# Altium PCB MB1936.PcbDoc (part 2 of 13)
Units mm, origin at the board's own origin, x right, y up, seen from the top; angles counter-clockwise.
Board outline 172 x 137 mm, 6 copper layers (Top Layer, Signal Layer 1, Signal Layer 2, Signal Layer 3, Signal Layer 4, Bottom Layer), stack 1.549 mm thick; 859 components, 672 nets, 3477 pads, 2222 vias.
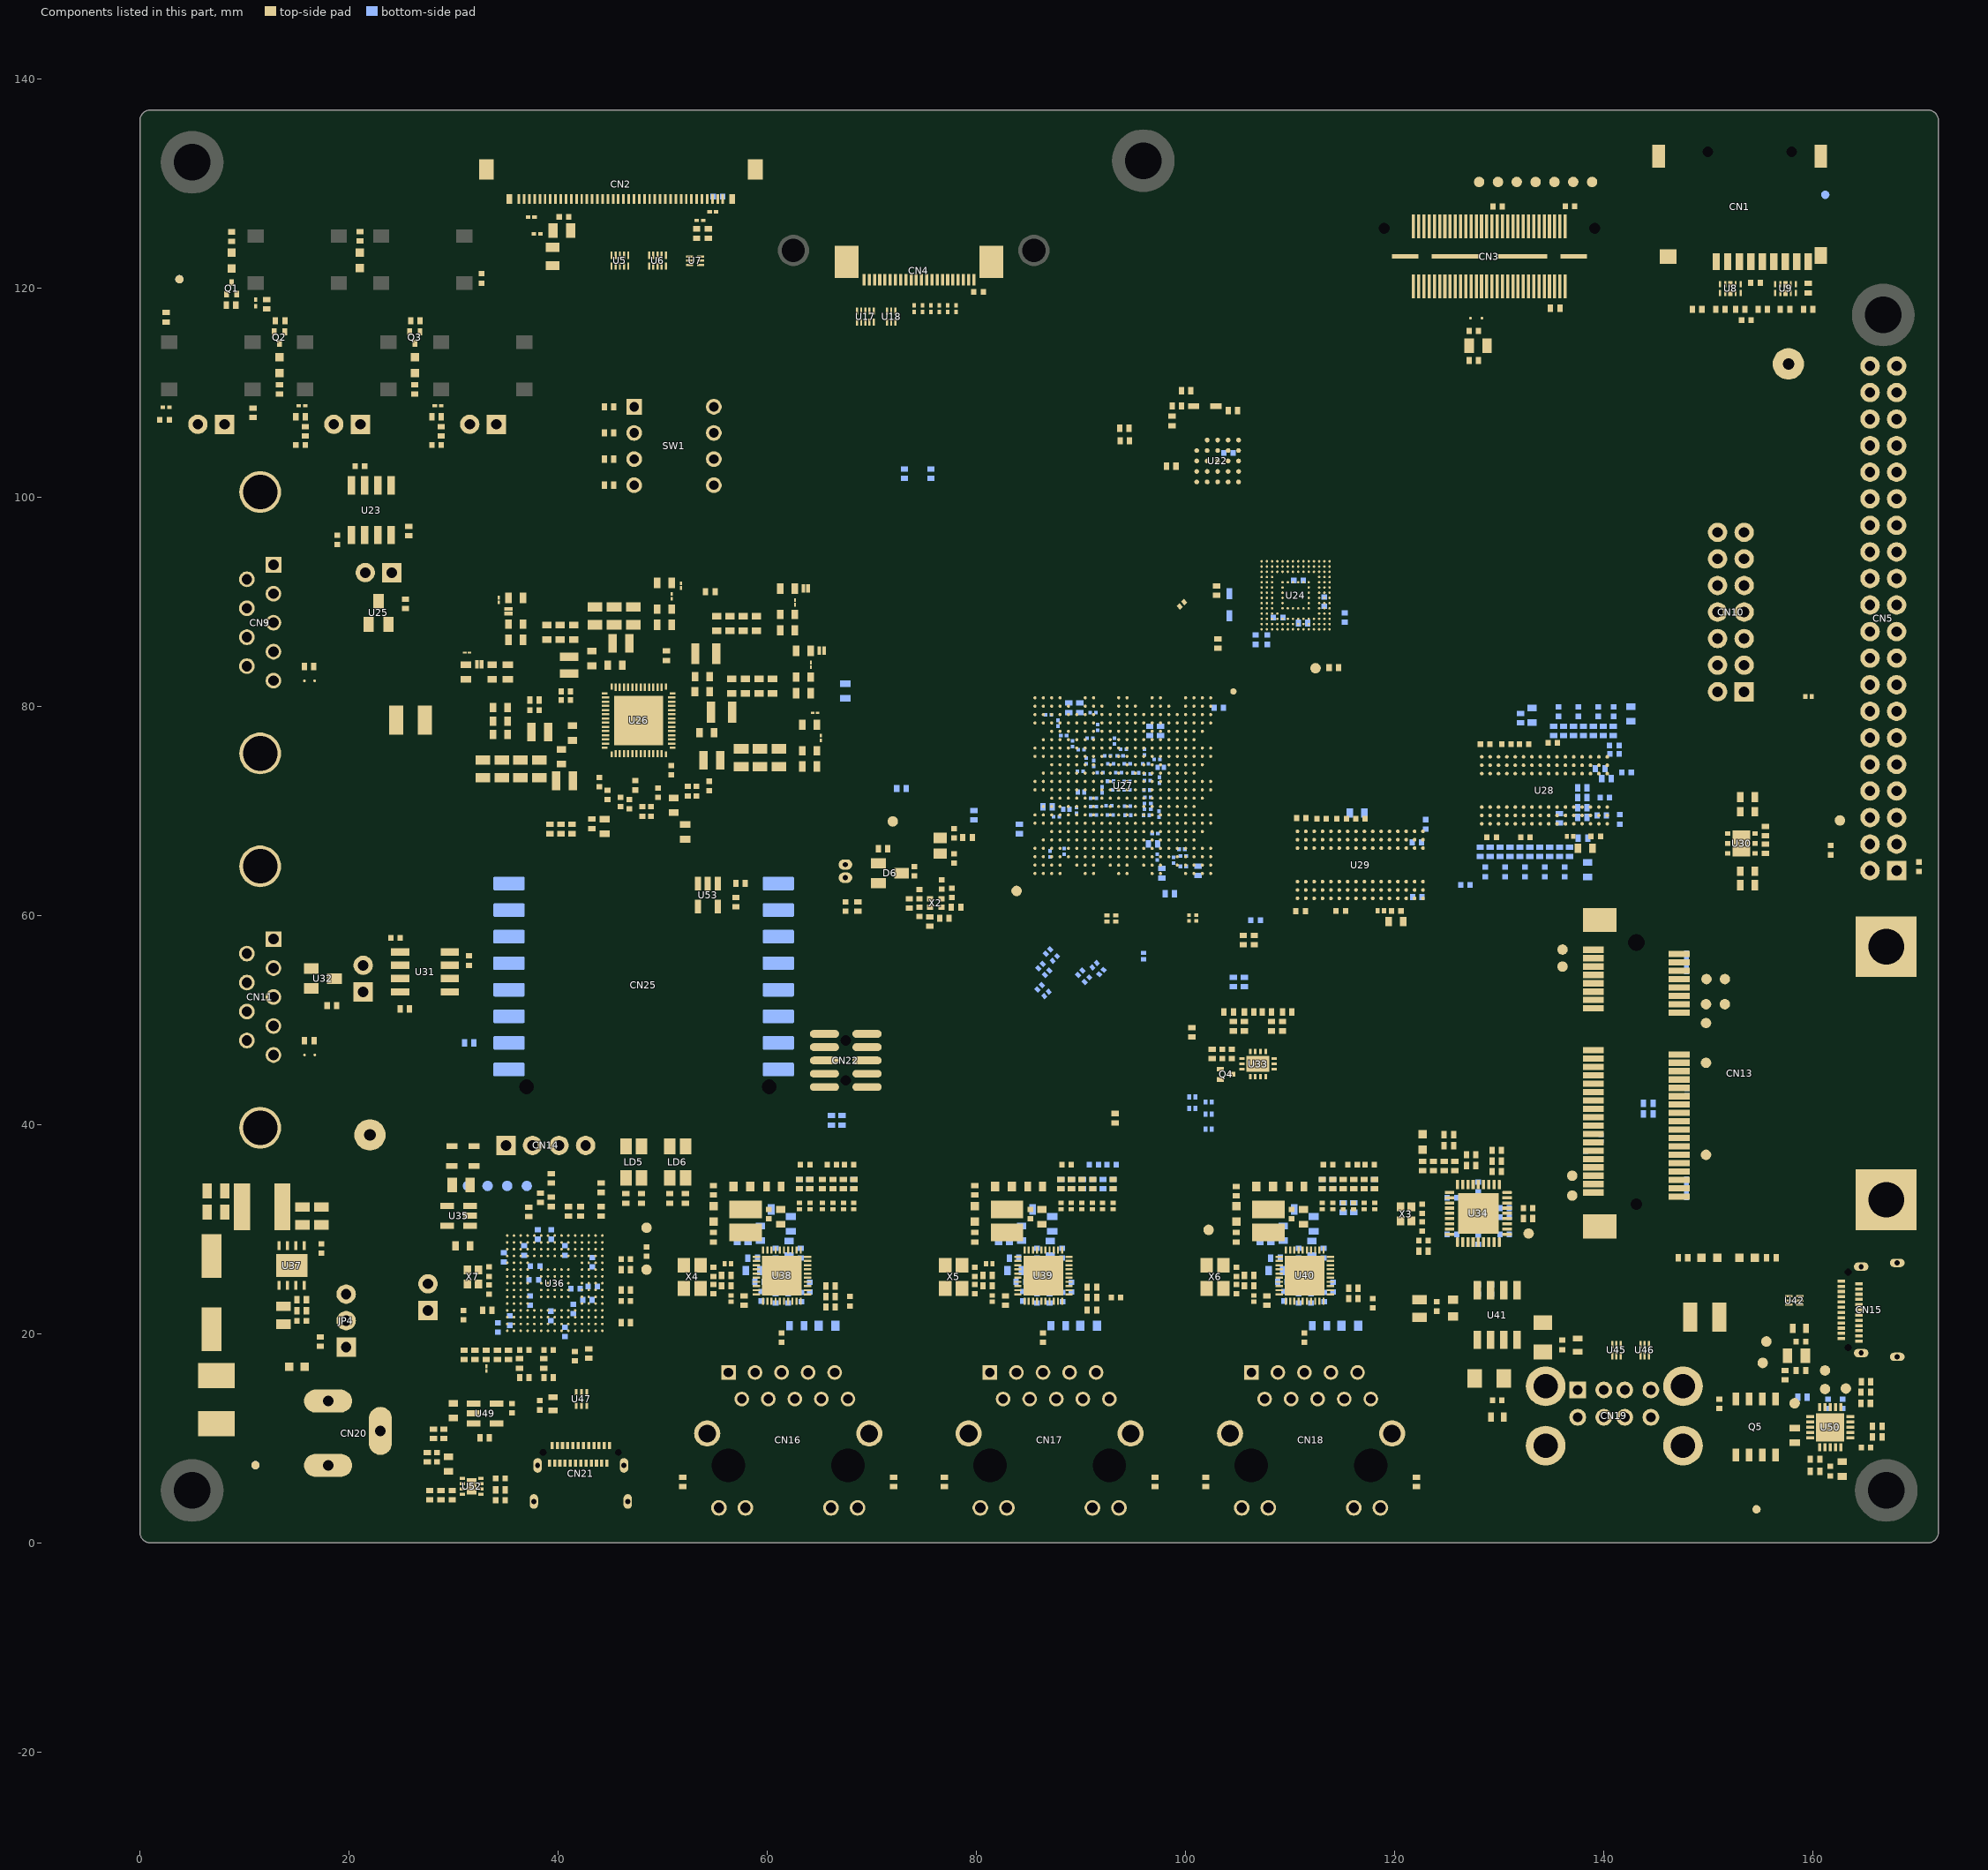
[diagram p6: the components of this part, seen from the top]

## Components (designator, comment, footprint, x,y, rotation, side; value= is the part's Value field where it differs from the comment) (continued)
C289 "Capacitor" C0402 36.75,27.95 r270 bottom value=100nF
C290 "Capacitor" C0402 40.65,27.95 r270 bottom value=100nF
C291 "" C0402 113.2,27.7 r90 bottom value=100nF
C292 "" C0402 110.8,27.7 r90 bottom value=100nF
C293 "" C0402 88.2,27.7 r90 bottom value=100nF
C294 "" C0402 85.8,27.7 r90 bottom value=100nF
C295 "" C0402 63.2,27.7 r90 bottom value=100nF
C296 "" C0402 60.8,27.7 r90 bottom value=100nF
C297 "Capacitor" C0402 34.8,27.3 r270 bottom value=100nF
C298 "Capacitor" C0402 43.25,26.825 r90 bottom value=100nF
C299 "Capacitor" C0402 37.8,26.45 r0 bottom value=100nF
C300 "" C0603 108.65,26.025 r180 bottom value=22uF
C301 "" C0603 83.65,26.025 r180 bottom value=22uF
C302 "" C0603 58.65,26.025 r180 bottom value=22uF
C303 "Capacitor" C0402 37.675,25.15 r0 bottom value=100nF
C304 "" C0402 109.25,24.95 r180 bottom value=100nF
C305 "" C0402 84.25,24.95 r180 bottom value=100nF
C306 "" C0402 59.25,24.95 r180 bottom value=100nF
C307 "" C0402 114.1,24.45 r270 bottom value=100nF
C308 "" C0402 89.075,24.45 r270 bottom value=100nF
C309 "" C0402 64.075,24.45 r270 bottom value=100nF
C310 "Capacitor" C0402 43.3,24.5 r180 bottom value=100nF
C311 "Capacitor" C0402 41.65,24.3 r180 bottom value=100nF
C312 "" C0402 109.445,23.57 r270 bottom value=100nF
C313 "" C0402 84.445,23.57 r270 bottom value=100nF
C314 "" C0402 59.445,23.57 r270 bottom value=100nF
C315 "" C0402 113.25,23.5 r270 bottom value=100nF
C316 "" C0402 88.25,23.5 r270 bottom value=100nF
C317 "" C0402 63.25,23.5 r270 bottom value=100nF
C318 "" C0402 112,23.375 r270 bottom value=100nF
C319 "" C0402 110.8,23.375 r270 bottom value=100nF
C320 "" C0402 87,23.375 r270 bottom value=100nF
C321 "" C0402 85.8,23.375 r270 bottom value=100nF
C322 "" C0402 62,23.375 r270 bottom value=100nF
C323 "" C0402 60.8,23.375 r270 bottom value=100nF
C324 "Capacitor" C0402 37.325,23.15 r270 bottom value=100nF
C325 "Capacitor" C0402 42.8,23.225 r180 bottom value=100nF
C326 "Capacitor" C0402 41.455,22.35 r90 bottom value=100nF
C327 "Capacitor" C0402 39.3,21.7 r90 bottom value=100nF
C328 "Capacitor" C0402 35.375,21.25 r90 bottom value=100nF
C329 "Capacitor" C0402 34.225,20.6 r90 bottom value=100nF
C330 "" C0603 112.825,20.75 r0 bottom value=22uF
C331 "" C0603 87.825,20.75 r0 bottom value=22uF
C332 "" C0603 62.825,20.75 r0 bottom value=22uF
C333 "Capacitor" C0402 40.65,20.175 r270 bottom value=100nF
C334 "Capacitor" C0402 162.85,13.3 r270 bottom value=100nF
C335 "Capacitor" C0402 161.45,13.3 r270 bottom value=4.7uF
C336 "Capacitor" C0402 76.675,62.95 r90 top value=10nF
CART-1 "Comment" Sheetbox_6L2S 36.315,-31.21 r0 top
CN1 "MR01A-01211" CON_MICROSD_ATOM_MR01A-01211 153,137 r180 top value=Connector_uSD-Card_MR01A-01211
CN2 "IPEX20455" CON_I-PEX_20455-040E-76 46,129 r180 top value=Socket_FFC/FPC_IPEX
CN3 "Socket QSH-030-01-F-D-A" CON_SAMTEC_QSH-030-01-F-D-A 129.05,123 r180 top locked value="Socket 30x2"
CN4 "2-1734592-2" CON_TE-CONNECTIVITY_2-1734592-2_INV 74.5,122.49 r180 top
CN5 "Header 20x2" CON_SAMTEC_TSW-120-07-G-D 166.725,88.4 r90 top
CN6 "Header 2x1" CON_SAMTEC_TSW-102-07-G-S 6.813,106.95 r180 top
CN7 "Header 2x1" CON_SAMTEC_TSW-102-07-G-S 19.813,106.95 r180 top
CN8 "Header 2x1" CON_SAMTEC_TSW-102-07-G-S 32.813,106.95 r180 top
CN9 "DB9_Header_male_2301843-2" CON_DB9-MALE_TYCO_2301843-2 4,87.98 r270 top locked value=Header_DB9_2301843-2
CN10 "Header 7x2" CON_SAMTEC_TSW-107-07-X-D 152.15,89 r90 top value="Jumper_Header 7x2"
CN11 "DB9_Header_male_2301843-2" CON_DB9-MALE_TYCO_2301843-2 4,52.185 r270 top locked value=Header_DB9_2301843-2
CN12 "" CON_MOLEX_53047-0210 67.475,64.225 r270 top value="Header 2x1"
CN13 "SOCKET_Mini_PCIE" CON_TE-CONNECTIVITY_2041119-1_HALF-CARD 143.1,57.4 r270 top value="Mini PCIE_2041119-1"
CN14 "Header 4x1" CON_SAMTEC_TSW-104-07-G-S 38.815,38 r0 top
CN15 "USB_TYPE_C_Receptacle" CON_USB-TYPEC_AMPHENOL_12401826E412A 163.36,22.275 r90 top value=USB_C_12401826E412A
CN16 "​New part for use of led pulled down on pin 13/14 , schematic more lisible." CON_RJ45_YD_48F-01GYDXNL_LED-P 62,0 r0 top value=RJ45_48F-01GYDXNL
CN17 "​New part for use of led pulled down on pin 13/14 , schematic more lisible." CON_RJ45_YD_48F-01GYDXNL_LED-P 87,0 r0 top value=RJ45_48F-01GYDXNL
CN18 "​New part for use of led pulled down on pin 13/14 , schematic more lisible." CON_RJ45_YD_48F-01GYDXNL_LED-P 112,0 r0 top value=RJ45_48F-01GYDXNL
CN19 "USB_DUAL_TYPEA_5600-3081" CON_DUAL-USB-TYPE-A_CONEXCON_5600-3081 141,-1.01 r0 top value=USB_A_5600-3081
CN20 "DC10B" CON_DC-POWER-SOCKET_CLIFF_FC68149_DC10B 18,0 r270 top value=Jack_DC-Power_DC10B
CN21 "USB_TYPE_C_Receptacle" CON_USB-TYPEC_AMPHENOL_12401826E412A 42.165,8.65 r0 top value=USB_C_12401826E412A
CN22 "Header 5x2" CON_SAMTEC_FTSH-105-01-L-DV-K 67.5,46.125 r270 top
CN25 "MIKROE-4319" SOCKET_MIKROBUS_MIKROE-4319_SMD_P254 48.175,54.15 r180 bottom
D1 "BAT60JFILM" DIO_SOD323 101.83,108.7 r180 top
D2 "SCHOTTKY_1A_2K" DIO_SOD323_1A_2K 30.9,37.925 r0 top value=BAT20JFILM
D3 "SCHOTTKY_1A_2K" DIO_SOD323_1A_2K 30.895,36.025 r0 top value=BAT20JFILM
D5 "BAT60JFILM" DIO_SOD323 104.175,89.7 r90 bottom
D6 "DIODE_3P_DUAL_COMMON_CATHODE" DIO_SOT23 71.725,64.025 r270 top value=BAT54CFILM
F1 "0ZCG0260FF2C" PTC_BEL-FUSE_1812_0ZCG0260FF2C 7.325,13.7 r90 top value="PTC FUSE 2.6A"
JP1 "Jumper_Header 2x1" CON_SAMTEC_TSW-102-07-G-S 22.819,92.771 r180 top value="Header 2x1"
JP2 "Jumper_Header 2x1" CON_SAMTEC_TSW-102-07-G-S 21.355,53.95 r90 top value="Header 2x1"
JP3 "Jumper_Header 2x1" CON_SAMTEC_TSW-102-07-G-S 27.55,23.495 r90 top value="Header 2x1"
JP4 "Jumper_Header 3x1" CON_SAMTEC_TSW-103-07-F-S 19.725,21.24 r90 top value="Header 3x1"
L1 "Inductor" IND_2016_MURATA_LQM2MPN2R2NG0 45.995,86.002 r180 top value=2.2uH
L2 "Inductor" IND_2520_TOKO_DFE252012P 54.115,85.027 r0 top value=0.68µH
L3 "Inductor" IND_2016_MURATA_LQM2MPN2R2NG0 41.05,83.902 r90 top value=0.68uH
L4 "Inductor" IND_2520_TOKO_DFE252012P 55.625,79.427 r0 top value=0.68µH
L5 "Inductor" IND_2016_MURATA_LQM2MPN2R2NG0 38.225,77.527 r180 top value=0.68uH
L6 "Inductor" IND_2016_MURATA_LQM2MPN2R2NG0 54.7,74.827 r0 top value=2.2uH
L7 "Inductor" IND_2016_MURATA_LQM2MPN2R2NG0 40.6,72.877 r180 top value=0.68uH
L8 "Inductor" IND_5040_WURTH_74404054033 11.7,32.125 r0 top value=3.3uH
L9 "" FIL_0603_H0P65 57.57,34.07 r180 top value="100R @ 100MHz"
L10 "" FIL_0603_H0P65 82.57,34.07 r180 top value="100R @ 100MHz"
L11 "" FIL_0603_H0P65 107.57,34.07 r180 top value="100R @ 100MHz"
L12 "BEAD" FIL_0603_H0P65 125.575,22.45 r270 top value="26R @ 100Mhz"
L13 "" FIL_0603_H0P65 115.72,20.75 r0 bottom value="100R @ 100MHz"
L14 "" FIL_0603_H0P65 90.72,20.75 r0 bottom value="100R @ 100MHz"
L15 "" FIL_0603_H0P65 65.72,20.75 r0 bottom value="100R @ 100MHz"
LD1 "LED_red" LED_0603_VISHAY_VLMS1300-GS08_RED_1A2K_H0P8 21.047,122.625 r270 top value=RED
LD2 "LED_green" LED_0603_OSRAM_LG-Q396-PS-35_GREEN_1A2K_H0P4 26.287,112.6 r90 top value=GREEN
LD3 "LED_orange" LED_0603_OSRAM_LO-Q976-PS-25_ORANGE_1A2K_H0P8 13.363,112.6 r90 top value=ORANGE
LD4 "" LED_0603_OSRAM_LB-Q39G-L2OO-35-1_BLUE_1A2K_H0P4 8.773,122.6 r270 top value=BLUE
LD5 "LED_BICOLOR" LED_BI-GR_WE-150141SV73110 47.225,36.4 r180 top value="Green / Red"
LD6 "LED_BICOLOR" LED_BI-GR_WE-150141SV73110 51.425,36.4 r180 top value="Green / Red"
LD7 "LED_green" LED_0603_OSRAM_LG-Q396-PS-35_GREEN_1A2K_H0P4 54.85,31.445 r90 top value=GREEN
LD8 "LED_green" LED_0603_OSRAM_LG-Q396-PS-35_GREEN_1A2K_H0P4 79.85,31.445 r90 top value=GREEN
LD9 "LED_green" LED_0603_OSRAM_LG-Q396-PS-35_GREEN_1A2K_H0P4 104.85,31.445 r90 top value=GREEN
LD10 "LED_green" LED_0603_OSRAM_LG-Q396-PS-35_GREEN_1A2K_H0P4 153.7,27.25 r180 top value=GREEN
LD11 "LED_green" LED_0603_OSRAM_LG-Q396-PS-35_GREEN_1A2K_H0P4 15.025,16.85 r180 top value=GREEN
LD12 "LED_red" LED_0603_VISHAY_VLMS1300-GS08_RED_1A2K_H0P8 122.675,38.325 r90 top value=RED
LE1 "" L1210_LQH 57.925,30.775 r90 top value=4.7uH
LE2 "" L1210_LQH 82.925,30.775 r90 top value=4.7uH
LE3 "" L1210_LQH 107.925,30.775 r90 top value=4.7uH
LED2 "" LED_0603_OSRAM_LB-Q39G-L2OO-35-1_BLUE_1A2K_H0P4 150.1,27.25 r0 top value=BLUE
LNK1 "link_200" LINK200#1 51.75,91.525 r0 top
LNK2 "link_200" LINK200#2 63.675,91.275 r90 top
LNK3 "link_200" LINK200#1 50.855,90.5 r0 top
LNK4 "link_200" LINK200#1 34.325,90.15 r180 top
LNK5 "link_200" LINK200#1 62.65,89.925 r180 top
LNK6 "link_200" LINK200#2 35.245,89.075 r180 top
LNK7 "link_200" LINK200#2 65.2,85.3 r90 top
LNK8 "link_200" LINK200#1 31.3,85.125 r90 top
LNK9 "link_200" LINK200#2 32.452,83.997 r90 top
LNK10 "link_200" LINK200#1 64.175,83.95 r180 top
LNK11 "link_200" LINK200#1 64.575,79.375 r270 top
LNK12 "link_200" LINK200#1 65.125,76.95 r0 top
LNK13 "link_200" LINK200#1 33.125,16.655 r0 top
MIRE1 "Comment" MIRE_PLACE_SMD_0P8MM 154.6,3.2 r0 top locked
MIRE2 "Comment" MIRE_PLACE_SMD_0P8MM 11.05,7.425 r0 top locked
MIRE3 "Comment" MIRE_PLACE_SMD_0P8MM 3.78,120.82 r0 top locked
MIRE4 "Comment" MIRE_PLACE_SMD_0P8MM 3.78,120.82 r180 bottom locked
MIRE5 "Comment" MIRE_PLACE_SMD_0P8MM 11.05,7.425 r180 bottom locked
MIRE6 "Comment" MIRE_PLACE_SMD_0P8MM 161.175,128.9 r180 bottom locked
Q1 "MOSFET_N-CHANNEL" MOS_SC89-3L 8.773,119.95 r0 top value=Si1062X
Q2 "MOSFET_N-CHANNEL" MOS_SC89-3L 13.363,115.25 r180 top value=Si1062X
Q3 "MOSFET_N-CHANNEL" MOS_SC89-3L 26.287,115.25 r180 top value=Si1062X
Q4 "MOSFET_N-CHANNEL" MOS_SC89-3L 103.875,44.79 r270 top value=Si1062X
Q5 "STL40DN3LLH5" PowerFLAT_5x6 154.52,11.075 r0 top
R1 "Resistor" R0402 53.25,125.195 r90 top value=10K
R2 "Resistor" R0402 54.35,125.195 r90 top value=0R
R3 "Resistor" R0402 21.047,124.925 r270 top value=360R
R4 "" R0402 8.773,124.9 r270 top value=120R
R5 "Resistor" R0805 39.475,123 r270 top value=0R
R6 "Resistor" R0402 159.55,119.975 r90 top value=0R
R7 "Resistor" R0402 12.123,118.425 r270 top value=10K
R8 "Resistor" R0402 8.723,118.35 r180 top value=100K
R9 "Resistor" R0402 135.35,118.05 r0 top value=10K
R10 "Resistor" R0402 148.925,117.95 r180 top value=47K
R11 "Resistor" R0402 151.15,117.95 r180 top value=47K
R12 "Resistor" R0402 153.05,117.95 r0 top value=47K
R13 "Resistor" R0402 155.19,117.95 r180 top value=10K
R14 "Resistor" R0402 157.325,117.95 r0 top value=47K
R15 "Resistor" R0402 159.55,117.95 r0 top value=47K
R16 "Resistor" R0402 13.413,116.85 r0 top value=100K
R17 "Resistor" R0402 26.338,116.85 r0 top value=100K
R18 "Resistor" R0402 127.573,113.05 r180 top value=0R
R19 "Resistor" R0402 13.363,110.3 r270 top value=300R
R20 "Resistor" R0402 26.287,110.3 r270 top value=270R
R21 "Resistor" R0402 100.05,110.15 r180 top value=0R
R22 "Resistor" R0402 99.159,108.7 r0 top value=0R
R23 "Resistor" R0402 104.516,108.275 r0 top value=10K
R24 "Resistor" R0402 15.363,107.675 r0 top value=100K
R25 "Resistor" R0402 28.363,107.675 r0 top value=100K
R26 "Resistor" R0402 2.5,117.187 r90 top value=100R
R27 "Resistor" R0402 98.709,107.275 r270 top value=10K
R28 "Resistor" R0402 15.813,106.275 r90 top value=330R
R29 "Resistor" R0402 28.813,106.275 r90 top value=330R
R30 "Resistor" R0402 10.813,108.062 r270 top value=1K
R31 "Resistor" R0402 94.155,106.575 r0 top value=1K5
R32 "Resistor" R0402 94.18,105.375 r0 top value=1K5
R33 "Resistor" R0402 98.634,102.95 r180 top value=10K
R34 "Resistor" R0402 25.721,96.756 r90 top value=10K
R35 "Resistor" R0603 50.155,91.777 r0 top value=0R
R36 "Resistor" R0603 61.93,91.252 r0 top value=0R
R37 "Resistor" R0402 102.975,91.05 r90 top value=10K
R38 "" R0402 54.55,90.95 r180 top value=0R
R39 "Resistor" R0603 35.945,90.352 r180 top value=0R
R40 "Resistor" R0402 25.399,89.771 r90 top value=120R
R41 "Resistor" R0603 50.155,87.777 r0 top value=330mR
R42 "Resistor" R0603 61.93,87.252 r0 top value=33mR
R43 "Resistor" R0603 35.945,86.352 r180 top value=100mR
R44 "Resistor" R0402 103.1,85.978 r270 top value=10K
R45 "Resistor" R0603 63.455,85.277 r0 top value=0R
R46 "" R0402 50.35,84.825 r270 top value=0R
R47 "Resistor" R0603 31.175,83.277 r90 top value=0R
R48 "Resistor" R0603 35.175,83.277 r90 top value=100mR
R49 "Resistor" R0402 114.175,83.685 r0 top value=10K
R50 "Resistor" R0402 16.187,83.8 r180 top value=1K
R51 "Resistor" R0603 63.455,81.227 r0 top value=33mR
R52 "Resistor" R0402 37.725,80.575 r180 top value=0R
R53 "Resistor" R0603 64.055,78.227 r0 top value=0R
R54 "Resistor" R0603 64.055,74.227 r0 top value=330mR
R55 "Resistor" R0603 153.755,71.3 r0 top value=0R
R56 "Resistor" R0603 44.45,68.502 r90 top value=0R
R57 "Resistor" R0402 43.225,68.752 r90 top value=0R
R58 "Resistor" R0603 52.15,67.975 r270 top value=0R
R59 "" R0402 39.225,68.25 r90 top value=0R
R60 "" R0402 40.275,68.25 r90 top value=0R
R61 "" R0402 41.325,68.25 r90 top value=0R
R62 "Resistor" R0402 155.455,68.05 r270 top value=82K
R63 "Resistor" R0201_H0P23 136.775,67.55 r180 top value=240R
R64 "" R0402 79.15,67.45 r180 top value=0R
R65 "Resistor" R0402 155.455,66.375 r270 top value=19K6
R66 "Resistor" R0402 68.675,60.845 r270 top value=20R
R67 "Resistor" R0402 71.075,66.375 r0 top value=0R
R68 "Resistor" R0402 44.875,108.625 r180 top value=1K
R69 "Resistor" R0603 153.75,62.875 r180 top value=0R
R70 "Resistor" R0402 73.575,61.125 r90 top value=10R
R71 "Resistor" R0402 44.875,106.125 r180 top value=1K
R72 "" R0402 78.05,60.775 r180 top value=1K
R73 "Resistor" R0201_H0P23 118.675,60.422 r180 top value=240R
R74 "Resistor" R0402 75.55,59.4 r270 top value=10K
R75 "" R0402 76.925,59.725 r0 top value=0R
R76 "Resistor" R0402 44.875,103.625 r180 top value=1K
R77 "Resistor" R0402 105.525,57.625 r270 top value=0R
R78 "Resistor" R0402 106.575,57.625 r270 top value=0R
R79 "Resistor" R0402 44.875,101.125 r180 top value=1K
R80 "Resistor" R0402 18.355,51.37 r0 top value=120R
R81 "Resistor" R0402 25.34,51.048 r0 top value=10K
R82 "Resistor" R0402 104.125,50.765 r180 top value=49R9
R83 "Resistor" R0402 106.075,50.765 r0 top value=49R9
R84 "Resistor" R0402 107.775,50.765 r0 top value=49R9
R85 "Resistor" R0402 109.725,50.765 r180 top value=49R9
R86 "Resistor" R0402 16.2,48.025 r180 top value=1K
R87 "Resistor" R0402 104.575,49.39 r90 top value=0R
R88 "Resistor" R0402 105.625,49.39 r90 top value=0R
R89 "Resistor" R0402 108.225,49.39 r90 top value=0R
R90 "Resistor" R0402 109.275,49.39 r90 top value=0R
R91 "Resistor" R0402 100.6,48.825 r90 top value=10K
R92 "Resistor" R0402 102.55,46.74 r270 top value=0R
R93 "" R0402 93.25,40.6 r270 top value=0R
R94 "Resistor" R0201_H0P23 159.575,80.925 r0 top value=22R
R95 "Resistor" R0402 125.175,39.025 r0 top value=100K
R96 "Resistor" R0402 72.825,72.125 r180 bottom value=10K
R97 "Resistor" R0402 125.175,37.975 r180 top value=100K
R98 "Resistor" R0402 129.75,37.525 r180 top value=100K
R99 "Resistor" R0402 127.3,37.105 r0 top value=100K
R100 "Resistor" R0402 129.75,36.5 r0 top value=100K
R101 "Resistor" R0402 122.675,36.025 r270 top value=1K
R102 "Resistor" R0402 123.7,36.025 r270 top value=100K
R103 "Resistor" R0402 124.725,36.025 r90 top value=10K
R104 "Resistor" R0402 125.75,36.025 r270 top value=10K
R105 "Resistor" R0402 127.3,36.08 r180 top value=100K
R106 "Resistor" R0402 129.75,35.5 r0 top value=10K
R107 "Resistor" R0402 39.35,34.85 r90 top value=10K
R108 "" R0402 91.125,34.3 r90 top value=4K7
R109 "" R0402 63.075,34.3 r90 top value=4K7
R110 "" R0402 64.075,34.3 r90 top value=4K7
R111 "" R0402 65.275,34.3 r90 top value=4K7
R112 "" R0402 66.275,34.3 r90 top value=4K7
R113 "" R0402 67.275,34.3 r270 top value=4K7
R114 "" R0402 68.275,34.3 r90 top value=4K7
R115 "" R0402 88.075,34.3 r90 top value=4K7
R116 "" R0402 89.075,34.3 r90 top value=4K7
R117 "" R0402 90.075,34.3 r90 top value=4K7
R118 "" R0402 93.075,34.3 r90 top value=4K7
R119 "" R0402 113.075,34.3 r90 top value=4K7
R120 "" R0402 114.075,34.3 r90 top value=4K7
R121 "" R0402 115.075,34.3 r90 top value=4K7
R122 "" R0402 116.075,34.3 r90 top value=4K7
R123 "" R0402 117.075,34.3 r270 top value=4K7
R124 "" R0402 118.075,34.3 r90 top value=4K7
R125 "Resistor" R0402 44.1,33.95 r90 top value=10K
R126 "Resistor" R0402 54.85,33.72 r90 top value=270R
R127 "Resistor" R0402 79.85,33.72 r90 top value=270R
R128 "Resistor" R0402 104.85,33.62 r90 top value=270R
R129 "Resistor" R0402 38.3,33 r90 top value=0R
R130 "Resistor" R0402 46.475,32.925 r90 top value=330R
R131 "Resistor" R0402 47.975,32.925 r270 top value=1K
R132 "Resistor" R0402 50.675,32.925 r270 top value=330R
R133 "Resistor" R0402 52.175,32.925 r270 top value=1K
R134 "Resistor" R0402 39.35,32.6 r90 top value=33R
R135 "Resistor" R0201_H0P23 63.075,32.2 r270 top value=22R
R136 "Resistor" R0201_H0P23 64.075,32.2 r270 top value=22R
R137 "Resistor" R0201_H0P23 65.275,32.2 r270 top value=22R
R138 "Resistor" R0201_H0P23 66.275,32.2 r270 top value=22R
R139 "Resistor" R0201_H0P23 67.275,32.2 r270 top value=22R
R140 "Resistor" R0201_H0P23 68.275,32.2 r270 top value=22R
R141 "Resistor" R0201_H0P23 88.075,32.2 r270 top value=22R
R142 "Resistor" R0201_H0P23 89.075,32.2 r270 top value=22R
R143 "Resistor" R0201_H0P23 90.075,32.2 r270 top value=22R
R144 "Resistor" R0201_H0P23 91.075,32.2 r270 top value=22R
R145 "Resistor" R0201_H0P23 92.075,32.2 r270 top value=22R
R146 "Resistor" R0201_H0P23 93.075,32.2 r270 top value=22R
R147 "Resistor" R0201_H0P23 113.075,32.2 r270 top value=22R
R148 "Resistor" R0201_H0P23 114.075,32.2 r270 top value=22R
R149 "Resistor" R0201_H0P23 115.075,32.2 r270 top value=22R
R150 "Resistor" R0201_H0P23 116.075,32.2 r270 top value=22R
R151 "Resistor" R0201_H0P23 117.075,32.2 r270 top value=22R
R152 "Resistor" R0201_H0P23 118.075,32.2 r270 top value=22R
R153 "Resistor" R0402 40.975,31.7 r90 top value=33R
R154 "Resistor" R0402 42.15,31.7 r90 top value=0R
R155 "Resistor" R0402 44.1,31.7 r270 top value=0R
R156 "Resistor" R0402 37.2,31.65 r90 top value=10K
R157 "Resistor" R0402 132.761,31 r0 top value=10K
R158 "" R0402 54.85,29.22 r90 top value=4K7
R159 "" R0402 79.85,29.22 r90 top value=4K7
R160 "" R0402 104.85,29.22 r90 top value=4K7
R161 "Resistor" R0201_H0P23 86.7,52.475 r225 bottom value=22R
R162 "Resistor" R0201_H0P23 92.475,59.7 r270 top value=22R
R163 "Resistor" R0201_H0P23 95.975,56.1 r270 bottom value=22R
R164 "Resistor" R0201_H0P23 86.05,53.125 r225 bottom value=22R
R165 "Resistor" R0201_H0P23 93.325,59.7 r270 top value=22R
R166 "Resistor" R0201_H0P23 102.2,39.55 r0 bottom value=22R
R167 "Resistor" R0201_H0P23 87.5,55.875 r225 bottom value=22R
R168 "Resistor" R0201_H0P23 89.925,54.5 r225 bottom value=22R
R169 "Resistor" R0201_H0P23 102.2,40.975 r0 bottom value=22R
R170 "Resistor" R0402 122.75,27.875 r0 top value=12K
R171 "" R0402 147.575,27.25 r180 top value=120R
R172 "Resistor" R0402 156.025,27.25 r180 top value=270R
R173 "Resistor" R0201_H0P23 86.775,54.5 r225 bottom value=22R
R174 "Resistor" R0201_H0P23 91.3,55.225 r225 bottom value=22R
R175 "Resistor" R0201_H0P23 100.65,41.55 r0 bottom value=22R
R176 "Resistor" R0201_H0P23 56.225,26.7 r0 top value=22R
R177 "Resistor" R0201_H0P23 81.225,26.7 r0 top value=22R
R178 "Resistor" R0201_H0P23 86.85,56.525 r225 bottom value=22R
R179 "Resistor" R0201_H0P23 90.575,53.85 r225 bottom value=22R
R180 "Resistor" R0201_H0P23 102.2,42.15 r0 bottom value=22R
R181 "Resistor" R0402 46.475,26.125 r0 top value=100R
R182 "" R0402 56.075,25.575 r0 top value=0R
R183 "" R0402 81.075,25.575 r0 top value=0R
R184 "" R0402 106.075,25.575 r0 top value=0R
R185 "Resistor" R0201_H0P23 86.125,55.15 r225 bottom value=22R
R186 "Resistor" R0201_H0P23 91.95,54.575 r225 bottom value=22R
R187 "Resistor" R0201_H0P23 100.65,42.625 r0 bottom value=22R
R188 "" R0402 56.075,24.575 r0 top value=0R
R189 "" R0402 81.075,24.575 r0 top value=0R
R190 "" R0402 106.075,24.575 r0 top value=0R
R191 "" R0402 66.045,24.55 r0 top value=1K5
R192 "" R0402 91.045,24.45 r0 top value=1K5
R193 "" R0402 116.045,24.35 r0 top value=1K5
R194 "Resistor" R0402 46.475,24.175 r0 top value=3K
R195 "" R0402 66.045,23.55 r0 top value=1K5
R196 "Resistor" R0201_H0P23 56.525,23.35 r90 top value=22R
R197 "Resistor" R0201_H0P23 81.525,23.35 r90 top value=22R
R198 "Resistor" R0201_H0P23 106.525,23.35 r90 top value=22R
R199 "" R0402 57.775,23.15 r270 top value=2K49
R200 "" R0402 82.775,23.15 r270 top value=2K49
R201 "" R0402 107.775,23.15 r270 top value=2K49
R202 "" R0402 91.045,23.45 r0 top value=1K5
R203 "" R0402 116.045,23.35 r0 top value=1K5
R204 "Resistor" R0402 15.475,23.25 r180 top value=20K
R205 "Resistor" R0402 66.045,22.55 r0 top value=10K
R206 "Resistor" R0402 91.045,22.25 r0 top value=10K
R207 "Resistor" R0402 33.225,22.225 r180 top value=33R
R208 "Resistor" R0402 15.475,22.2 r180 top value=110K
R209 "Resistor" R0402 46.475,21.05 r0 top value=33R
R210 "Resistor" R0402 17.25,19.25 r90 top value=270R
R211 "Resistor" R0402 42.925,18.105 r90 top value=0R
R212 "Resistor" R0402 31,17.975 r270 top value=0R
R213 "Resistor" R0402 32.05,17.975 r270 top value=10K
R214 "Resistor" R0402 33.125,17.975 r270 top value=10K
R215 "Resistor" R0402 34.2,17.975 r270 top value=10K
R216 "Resistor" R0402 35.25,17.975 r270 top value=5K1
R217 "Resistor" R0402 36.305,17.15 r270 top value=100K
R218 "Resistor" R0402 38.625,17.15 r270 top value=100K
R219 "Resistor" R0402 158.85,16.475 r0 top value=140K
R220 "Resistor" R0402 157.325,16.025 r90 top value=10K
R221 "Resistor" R0402 36.755,15.8 r0 top value=5K1
R222 "Resistor" R0402 39.075,15.8 r0 top value=5K1
R223 "Resistor" R0402 165.045,13.325 r0 top value=10K
R224 "Resistor" R0402 166.145,11.125 r0 top value=1K5
R225 "Resistor" R0603 158.25,10.275 r270 top value=22mR
R226 "Resistor" R0402 28.07,10.425 r90 top value=47K
R227 "Resistor" R0402 29.075,10.425 r270 top value=100K
R228 "Resistor" R0402 166.145,10.125 r0 top value=1K5
R229 "Resistor" R0402 32.975,10.05 r0 top value=100K
R230 "Resistor" R0402 27.475,8.175 r90 top value=47K
R231 "Resistor" R0402 160.2,8 r180 top value=24K
R232 "Resistor" R0402 160.2,6.845 r0 top value=100K
R233 "" R0402 51.925,5.825 r90 top value=510R
R234 "" R0402 72.075,5.825 r270 top value=510R
R235 "" R0402 76.925,5.825 r90 top value=510R
R236 "" R0402 97.075,5.825 r270 top value=510R
R237 "" R0402 101.925,5.825 r90 top value=510R
R238 "" R0402 122.075,5.825 r270 top value=510R
R239 "Resistor" R0402 34.475,5.05 r180 top value=100K
R240 "Resistor" R0402 27.72,4.55 r270 top value=1K3
R241 "Resistor" R0402 28.795,4.55 r270 top value=1K8
R242 "Resistor" R0402 29.87,4.55 r270 top value=3K9
R243 "Resistor" R0402 57.438,63.063 r180 top value=470K
R244 "Resistor" R0402 57,61.25 r90 top value=560K
R245 "Resistor" R0402 75.649,102.225 r90 bottom value=1K5
R246 "Resistor" R0402 73.109,102.225 r90 bottom value=1K5
R247 "Resistor" R0201_H0P23 99.65,89.75 r45 top value=22R
R248 "Resistor" R0402 111.225,87.95 r0 bottom value=10K
R249 "Resistor" R0603 67.45,81.45 r270 bottom value=0R
R250 "Resistor" R0402 89.875,79.85 r90 bottom value=200R
R251 "Resistor" R0402 88.825,79.85 r90 bottom value=200R
R252 "Resistor" R0402 132.025,78.85 r270 bottom value=10K
R253 "Resistor" R0402 140.9,77.625 r90 bottom value=56R
R254 "Resistor" R0402 139.95,77.625 r90 bottom value=56R
R255 "Resistor" R0402 139,77.625 r90 bottom value=56R
R256 "Resistor" R0402 138.05,77.625 r90 bottom value=56R
R257 "Resistor" R0402 137.1,77.625 r90 bottom value=56R
R258 "Resistor" R0402 136.15,77.625 r90 bottom value=56R
R259 "Resistor" R0402 135.2,77.625 r90 bottom value=56R
R260 "Resistor" R0402 97.6,77.625 r90 bottom value=1K5
R261 "Resistor" R0402 96.575,77.625 r90 bottom value=1K5
R262 "Resistor" R0201_H0P23 97.624,74.149 r0 bottom value=240R
R263 "Resistor" R0402 139.65,74.025 r0 bottom value=56R
R264 "Resistor" R0402 140.25,73.075 r0 bottom value=56R
R265 "Resistor" R0402 137.95,72.2 r0 bottom value=56R
R266 "Resistor" R0402 137.95,71.25 r0 bottom value=56R
R267 "" R0402 86.8,70.375 r180 bottom value=0R
R268 "Resistor" R0402 137.95,70.3 r0 bottom value=56R
R269 "" R0402 79.763,69.563 r270 bottom value=0R
R270 "Resistor" R0402 135.75,69.275 r90 bottom value=100R
R271 "Resistor" R0402 137.95,69.35 r0 bottom value=56R
R272 "Resistor" R0402 84.1,68.25 r270 bottom value=10K
R273 "Resistor" R0402 138,67.375 r0 bottom value=56R
R274 "Resistor" R0402 96.9,66.825 r180 bottom value=200R
R275 "Resistor" R0402 129.12,66.08 r270 bottom value=56R
R276 "Resistor" R0402 136.725,66.075 r270 bottom value=56R
R277 "Resistor" R0402 135.775,66.075 r270 bottom value=56R
R278 "Resistor" R0402 134.825,66.075 r270 bottom value=56R
R279 "Resistor" R0402 133.875,66.075 r270 bottom value=56R
R280 "Resistor" R0402 132.925,66.075 r270 bottom value=56R
R281 "Resistor" R0402 131.975,66.075 r270 bottom value=56R
R282 "Resistor" R0402 131.025,66.075 r270 bottom value=56R
R283 "Resistor" R0402 130.075,66.075 r270 bottom value=56R
R284 "Resistor" R0402 128.175,66.075 r270 bottom value=56R
R285 "Resistor" R0402 101.2,64.25 r90 bottom value=200R
R286 "" R0402 97.725,64.025 r90 bottom value=0R
R287 "Resistor" R0402 98.5,62.075 r0 bottom value=200R
R288 "Resistor" R0402 105.625,53.625 r270 bottom value=0R
R289 "" R0402 31.5,47.813 r0 bottom value=0R
R290 "Resistor" R0402 144.25,42.025 r180 bottom value=0R
R291 "Resistor" R0402 144.25,41 r180 bottom value=0R
R292 "" R0402 67.15,40.4 r270 bottom value=4K7
R293 "" R0402 66.125,40.4 r270 bottom value=4K7
R294 "" R0402 92.1,34.3 r270 bottom value=4K7
R295 "" R0402 91.125,34.3 r270 bottom value=4K7
R296 "" R0402 90.15,34.3 r270 bottom value=4K7
R297 "" R0402 118.075,34.3 r270 bottom value=4K7
R298 "" R0402 114.075,34.3 r270 bottom value=4K7
R299 "" R0402 113.075,34.3 r270 bottom value=4K7
R300 "" R0402 93.075,34.3 r270 bottom value=4K7
R301 "" R0402 89.075,34.3 r270 bottom value=4K7
R302 "" R0402 88.075,34.3 r270 bottom value=4K7
R303 "" R0402 68.275,34.3 r270 bottom value=4K7
R304 "" R0402 64.075,34.3 r270 bottom value=4K7
R305 "" R0402 63.075,34.3 r270 bottom value=4K7
R306 "" R0402 116.075,32.05 r90 bottom value=4K7
R307 "" R0402 115.075,32.05 r90 bottom value=4K7
R308 "" R0603 109.675,31.875 r0 bottom value=0R
R309 "" R0603 84.675,31.875 r0 bottom value=0R
R310 "" R0603 59.675,31.875 r0 bottom value=0R
R311 "" R0603 112.25,30.5 r90 bottom value=0R
R312 "" R0603 87.25,30.5 r90 bottom value=0R
R313 "" R0603 62.25,30.5 r90 bottom value=0R
R314 "" R0402 108.15,29.175 r90 bottom value=1K5
R315 "" R0402 107.125,29.175 r270 bottom value=4K7
R316 "" R0402 83.15,29.175 r90 bottom value=1K5
R317 "" R0402 82.125,29.175 r270 bottom value=4K7
R318 "" R0402 58.15,29.175 r90 bottom value=1K5
R319 "" R0402 57.125,29.175 r270 bottom value=4K7
R320 "" R0402 108.6,27.2 r180 bottom value=4K7
R321 "" R0402 83.6,27.2 r180 bottom value=4K7
R322 "" R0402 58.6,27.2 r180 bottom value=4K7
R323 "Resistor" R0402 129.16,24.225 r270 bottom value=10K
R324 "Resistor" R0402 127.89,24.225 r270 bottom value=10K
R325 "Resistor" R0402 159,13.925 r0 bottom value=1M
R326 "Resistor" R0402 165.05,14.4 r180 top value=0R
R327 "Resistor" R0402 165.075,15.4 r180 top value=100K
R328 "Resistor" R0402 104.575,53.625 r270 bottom value=0R
SB1 "SB_ON" SOLDER-BRIDGE_R0603-0R 127.85,117.1 r180 top
SB2 "SB_ON" SOLDER-BRIDGE_R0402-0R 16.262,82.425 r180 top
SB3 "SB_ON" SOLDER-BRIDGE_R0402-0R 16.275,46.65 r180 top
SW1 "76SB04ST" SWI_GRAYHILL-INC_76SB04ST 51.075,104.875 r270 top
TP1 "Test Point" TP_SMD_1MM 128.075,130.125 r90 top
TP2 "Test Point" TP_SMD_1MM 129.875,130.125 r90 top
TP3 "Test Point" TP_SMD_1MM 131.675,130.125 r90 top
TP4 "Test Point" TP_SMD_1MM 133.475,130.125 r90 top
TP5 "Test Point" TP_SMD_1MM 135.275,130.125 r90 top
TP6 "Test Point" TP_SMD_1MM 137.075,130.125 r90 top
TP7 "Test Point" TP_SMD_1MM 138.875,130.125 r90 top
TP8 "Test_pin_conn_black" TP_PTH-1P02MM_TEST-TERMINAL_RS_101-2391_BLACK 157.65,112.725 r90 top value=TP
TP9 "Test Point" TP_SMD_1MM 112.43,83.629 r90 top
TP10 "Test Point" TP_SMD_0-6MM 104.575,81.4 r90 top
TP11 "Test Point" TP_SMD_1MM 162.575,69.075 r90 top
TP12 "Test Point" TP_SMD_1MM 72,68.975 r90 top
TP13 "Test Point" TP_SMD_1MM 83.838,62.335 r90 top
TP14 "Test Point" TP_SMD_1MM 136.05,56.725 r90 top
TP15 "Test Point" TP_SMD_1MM 136.05,55.1 r90 top
TP16 "Test Point" TP_SMD_1MM 149.818,53.9 r90 top
TP17 "Test Point" TP_SMD_1MM 151.575,53.9 r90 top
TP18 "Test Point" TP_SMD_1MM 149.775,51.5 r90 top
TP19 "Test Point" TP_SMD_1MM 151.575,51.5 r90 top
TP20 "Test Point" TP_SMD_1MM 149.775,49.7 r90 top
TP21 "Test Point" TP_SMD_1MM 149.775,45.9 r90 top
TP22 "Test_pin_conn_black" TP_PTH-1P02MM_TEST-TERMINAL_RS_101-2391_BLACK 22,39 r90 top value=TP
TP23 "Test Point" TP_SMD_1MM 149.775,37.1 r90 top
TP24 "Test Point" TP_SMD_1MM 136.975,35.1 r90 top
TP25 "Test Point" TP_SMD_1MM 136.975,33.2 r90 top
TP26 "Test Point" TP_SMD_1MM 33.25,34.125 r90 bottom
TP27 "Test Point" TP_SMD_1MM 37,34.125 r90 bottom
TP28 "Test Point" TP_SMD_1MM 31.375,34.125 r90 bottom
TP29 "Test Point" TP_SMD_1MM 35.125,34.125 r90 bottom
TP30 "Test Point" TP_SMD_1MM 48.45,30.125 r90 top
TP31 "Test Point" TP_SMD_1MM 102.2,29.925 r270 top
TP32 "Test Point" TP_SMD_1MM 132.811,29.575 r90 top
TP33 "Test Point" TP_SMD_1MM 48.45,26.125 r270 top
TP34 "Test Point" TP_SMD_1MM 155.546,19.25 r270 top
TP35 "Test Point" TP_SMD_1MM 155.193,17.2 r90 top
TP36 "Test Point" TP_SMD_1MM 161.15,16.475 r0 top
TP37 "Test Point" TP_SMD_1MM 163.15,14.75 r0 top
TP38 "Test Point" TP_SMD_1MM 161.15,14.704 r0 top
TP39 "Test Point" TP_SMD_1MM 158.25,13.345 r270 top
U1 "ESD-TRANSIL" ESD_ST0201 54.8,127.275 r180 top value=ESDALC6V1-1U2
U2 "ESD-TRANSIL" ESD_ST0201 37.425,126.75 r180 top value=ESDALC6V1-1U2
U3 "ESD-TRANSIL" ESD_ST0201 53.563,126.45 r0 top value=ESDALC6V1-1U2
U4 "ESD-TRANSIL" ESD_ST0201 37.975,125.175 r180 top value=ESDALC6V1-1U2
U5 "ECMF4-40A100N10" ESD_UQFN-10L_2P25X1P4_P040 45.9,122.6 r180 top
U6 "ECMF4-40A100N10" ESD_UQFN-10L_2P25X1P4_P040 49.5,122.6 r180 top
U7 "ECMF2-40A100N6" ESD_UQFN-6L_1P45X1P4_P040 53.1,122.6 r270 top
U8 "HSP051-4M10" ESD_UQFN-10L_2P5X1_P050 152.1,119.93 r0 top
U9 "HSP051-4M10" ESD_UQFN-10L_2P5X1_P050 157.375,119.93 r0 top
U10 "ESD-TRANSIL" ESD_ST0201 11.073,118.563 r270 top value=ESDALC6V1-1U2
U11 "ESD-TRANSIL" ESD_ST0201 74.06,118 r270 top value=ESDALC6V1-1U2
U12 "ESD-TRANSIL" ESD_ST0201 74.86,118 r270 top value=ESDALC6V1-1U2
U13 "ESD-TRANSIL" ESD_ST0201 75.66,118 r270 top value=ESDALC6V1-1U2
U14 "ESD-TRANSIL" ESD_ST0201 76.46,118 r270 top value=ESDALC6V1-1U2
U15 "ESD-TRANSIL" ESD_ST0201 77.26,118 r270 top value=ESDALC6V1-1U2
U16 "ESD-TRANSIL" ESD_ST0201 78.06,118 r270 top value=ESDALC6V1-1U2
U17 "ECMF4-40A100N10" ESD_UQFN-10L_2P25X1P4_P040 69.375,117.25 r180 top
U18 "ECMF2-40A100N6" ESD_UQFN-6L_1P45X1P4_P040 71.85,117.25 r180 top
U19 "ESD-TRANSIL" ESD_ST0201 15.513,108.725 r180 top value=ESDALC6V1-1U2
U20 "ESD-TRANSIL" ESD_ST0201 28.513,108.725 r180 top value=ESDALC6V1-1U2
U21 "ESD-TRANSIL" ESD_ST0201 2.5,108.563 r180 top value=ESDALC6V1-1U2
U22 "MX25L51245G" ICC_BGA24_5X5-BALL-ARRAY_6X8_P1 103.066,103.441 r0 top
U23 "MCP2562FD" ICC_SO8_5X4_P127 22.129,98.736 r180 top value=MCP2562FDT-H/SN
U24 "eMMC_THGBMTG5D1LBAIL" ICC_P-WFBGA153_13X11P5_P050 110.525,90.6 r0 top locked value=THGBMTG5D1LBAIL
U25 "ESD-TRANSIL-DUAL-BIDIR" ESD_SOT23 22.819,88.921 r0 top value=ESDCAN24-2BLY
U26 "STPMIC2" ICC_QFN56-EPAD_6P5X6P5_P040 47.7,78.627 r90 top value=STPMIC25A
U27 "STM32MP257FAI3" ICC_LFBGA436_18X18_P080_H1P70_STM32MP257_CODE-B0D1 94,72.4 r0 top locked
U28 "MT40A1G16TB-062E IT:F" ICC_FBGA96_TB_7P5X13_P080 134.325,71.95 r270 top locked
U29 "MT40A1G16TB-062E IT:F" ICC_FBGA96_TB_7P5X13_P080 116.7,64.825 r270 top locked
U30 "ST1L05BPUR" ICC_DFN6-EPAD_3X3_P095 153.155,66.875 r270 top
U31 "MCP2562FD" ICC_SO8_5X4_P127 27.265,54.585 r90 top value=MCP2562FDT-H/SN
U32 "ESD-TRANSIL-DUAL-BIDIR" ESD_SOT23 17.505,53.95 r270 top value=ESDCAN24-2BLY
U33 "DSC557-0344FI0-T" ICC_QFN14-EPAD_3P2X2P5_P050 106.925,45.79 r0 top
U34 "USB2514B-AEZC" ICC_QFN36-EPAD_6X6_P050 128,31.5 r0 top
U35 "ST730M33R" ICC_SOT23-5L_H1P45 30.47,31.275 r90 top
U36 "STLINK-V3EC" ICC_UFBGA201_176+25_10X10_P065 39.675,24.825 r0 top value=STM32F723IEK6
U37 "ST1S40IPUR" ICC_VFQFPN8-EPAD_4X4_P080 14.525,26.5 r0 top
U38 "RTL8211F-CG" ICC_QFN40-EPAD_5X5_P040 61.4,25.55 r90 top
U39 "RTL8211F-CG" ICC_QFN40-EPAD_5X5_P040 86.4,25.55 r90 top
U40 "RTL8211F-CG" ICC_QFN40-EPAD_5X5_P040 111.4,25.55 r90 top
U41 "STMPS2252MTR" ICC_SO8_5X4_P127 129.795,21.775 r180 top
U42 "ECMF2-40A100N6" ESD_UQFN-6L_1P45X1P4_P040 158.225,23.175 r90 top
U43 "ESD-TRANSIL" ESD_QFN1610_2N_1K_2A 158.7,20.5 r180 top locked value=ESDA25P35-1U1M
U44 "ESD-TRANSIL" ESD_QFN1610_2N_1K_2A 137.5,18.9 r90 top value=ESDA7P120-1U1M
U45 "ECMF2-40A100N6" ESD_UQFN-6L_1P45X1P4_P040 141.2,18.425 r0 top
U46 "ECMF2-40A100N6" ESD_UQFN-6L_1P45X1P4_P040 143.9,18.425 r0 top
U47 "​" ESD_QFN-6L_1P7X1P5_P050 42.225,13.764 r0 top value=ECMF02-2AMX6
U48 "ESD-TRANSIL" ESD_QFN1610_2N_1K_2A 39.5,13.3 r90 top value=ESDA25P35-1U1M
U49 "STMPS2151STR" MOS_SOT23-5L 33.025,12.375 r270 top
U50 "TCPP03-M20" ICC_QFN20-EPAD_4X4_P050 161.65,11.05 r270 top
U51 "ESD-TRANSIL" ESD_QFN1610_2N_1K_2A 129.82,12.025 r180 top value=ESDA7P120-1U1M
U52 "TPS259535DSG" ICC_WSON8-EPAD_2X2_P050 31.725,5.4 r180 top
U53 "TSV631AILT" AOP_SOT23-5L_H1P45 54.312,61.938 r180 top
X1 "XTAL_2_PINS" CRY_NX2012SA_2P 76.525,66.65 r270 top value=32.768KHz
X2 "OSCILLATOR_4_PINS" CRY_NZ1612SH_4P 76.098,61.176 r0 top value=40MHz
X3 "XTAL_4_PINS" CRY_NX2016SA_4P 121.08,31.45 r90 top value=24MHz
X4 "XTAL_4_PINS" CRY_NX3225HA_4P 52.825,25.425 r270 top value=25MHz
X5 "XTAL_4_PINS" CRY_NX3225HA_4P 77.825,25.425 r270 top value=25MHz
X6 "XTAL_4_PINS" CRY_NX3225HA_4P 102.825,25.425 r270 top value=25MHz
X7 "XTAL_4_PINS" CRY_NX2016SA_4P 31.85,25.425 r270 top value=24MHz

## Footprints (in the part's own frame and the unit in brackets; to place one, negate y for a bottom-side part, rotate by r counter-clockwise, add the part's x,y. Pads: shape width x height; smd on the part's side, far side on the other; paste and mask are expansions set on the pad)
AOP_SOT23-5L_H1P45 [mm]
  rect 0.6x1.3 smd mask+0.05: 1(-0.95,-1.1) 2(0,-1.1) 3(0.95,-1.1) 4(0.95,1.1) 5(-0.95,1.1)
  silkscreen extent -1.75,-1.68 1.6,0.97, body extent -1.52,-1.25 1.52,1.25, height 1.45
C0201_H0P3 [mm] "MCD-00699"
  rect 0.4x0.5 smd mask+0.05: 1(-0.3,0) 2(0.3,0)
  body extent -0.32,-0.17 0.32,0.17, height 0.33
C0201_H0P5 [mm] "MCD-01534"
  rect 0.4x0.5 smd mask+0.05: 1(-0.3,0) 2(0.3,0)
  body extent -0.35,-0.2 0.35,0.2, height 0.55
C0201_MURATA_GRM033_H0P3 [mm] "GRM033R60J105ME11"
  rect 0.35x0.35 smd mask+0.05: 1(-0.275,0) 2(0.275,0)
  body extent -0.32,-0.17 0.32,0.17, height 0.33
C0402 [mm]
  rect 0.51x0.56 smd mask+0.05: 1(-0.45,0) 2(0.45,0)
  body extent -0.5,-0.3 0.5,0.3, height 0.4
C0603 [mm]
  rect 0.64x0.89 smd mask+0.05: 1(-0.7,0) 2(0.7,0)
  silkscreen extent -0.9,-0.55 1.05,0.55, body extent -0.9,-0.5 0.9,0.5, height 1.4
C0805 [mm]
  rect 0.9x1.4 smd mask+0.05: 1(-0.85,0) 2(0.85,0)
  silkscreen extent -1.3,-0.77 1.3,0.77, body extent -1.1,-0.7 1.1,0.7, height 1.35
C0805_H0P85 [mm] "MCD-01525"
  rect 0.9x1.4 smd mask+0.05: 1(-0.85,0) 2(0.85,0)
  silkscreen extent -1.3,-0.77 1.3,0.77, body extent -1.1,-0.73 1.1,0.73, height 0.95
C1206_H1P6 [mm]
  rect 1.4x1.78 smd mask+0.05: 1(-1.4,0) 2(1.4,0)
  silkscreen extent -2.12,-0.97 2.15,0.97, body extent -1.7,-0.9 1.7,0.9, height 1.8
CON_DB9-MALE_TYCO_2301843-2 [mm] "MCD-00127"
  rect 1.5x1.5 / inner round 1.5 / far side rect 1.5x1.5 hole 1 mask+0.05: 1(-5.54,8.77)
  round 1.5 hole 1 mask+0.05: 2(-2.77,8.77) 3(0,8.77) 4(2.77,8.77) 5(5.54,8.77) 6(-4.155,6.23) 7(-1.385,6.23) 8(1.385,6.23) 9(4.155,6.23)
  round 4 hole 3.3 mask+0.05: MT1(-12.5,7.5) MT2(12.5,7.5)
  silkscreen extent -15.5,-10.3 15.5,10.6, body extent -15.5,-10.3 15.5,10.6, height 13.8
CON_DC-POWER-SOCKET_CLIFF_FC68149_DC10B [mm]
  oval 2.2x4.6 hole 1 slot 3.5 at 90 deg mask+0.05: 1(-13.55,0) 3(-7.4,0)
  oval 4.6x2.2 hole 1 slot 3.5 at 0 deg mask+0.05: 2(-10.7,5)
  silkscreen extent -14.2,-4.6 0,4.6, body extent -14.3,-4.6 0.2,5.27, height 11
CON_DUAL-USB-TYPE-A_CONEXCON_5600-3081 [mm]
  round 1.6 hole 0.92: B1(-3.5,13.01) B2(-1,13.01) B3(1,13.01) B4(3.5,13.01) T2(-1,15.63) T3(1,15.63) T4(3.5,15.63)
  round 3.8 hole 2.33: CH1(6.57,10.3) CH2(-6.57,10.3) CH3(-6.57,15.98) CH4(6.57,15.98)
  rect 1.6x1.6 hole 0.92: T1(-3.5,15.63)
  silkscreen extent -7.3,-0.4 7.3,17.85, body extent -7.83,-0.6 7.87,17.85, height 16.2
CON_I-PEX_20455-040E-76 [mm] "MCD-03562"
  rect 0.25x0.9 smd mask+0.05: 1(-9.75,0.5) 2(-9.25,0.5) 3(-8.75,0.5) 4(-8.25,0.5) 5(-7.75,0.5) 6(-7.25,0.5) 7(-6.75,0.5) 8(-6.25,0.5) 9(-5.75,0.5) 10(-5.25,0.5) 11(-4.75,0.5) 12(-4.25,0.5) 13(-3.75,0.5) 14(-3.25,0.5) 15(-2.75,0.5) 16(-2.25,0.5) 17(-1.75,0.5) 18(-1.25,0.5) 19(-0.75,0.5) 20(-0.25,0.5) 21(0.25,0.5) 22(0.75,0.5) 23(1.25,0.5) 24(1.75,0.5) 25(2.25,0.5) 26(2.75,0.5) 27(3.25,0.5) 28(3.75,0.5) 29(4.25,0.5) 30(4.75,0.5) 31(5.25,0.5) 32(5.75,0.5) 33(6.25,0.5) 34(6.75,0.5) 35(7.25,0.5) 36(7.75,0.5) 37(8.25,0.5) 38(8.75,0.5) 39(9.25,0.5) 40(9.75,0.5)
  rect 1.4x1.9 smd mask+0.05: 41(-12.85,-2.32) 44(12.85,-2.32)
  rect 0.55x0.9 smd mask+0.05: 42(-10.65,0.5) 43(10.65,0.5)
  silkscreen extent -13.13,-2.78 13.13,0.92, body extent -13.13,-3.05 13.12,0.9, height 1.03
CON_MICROSD_ATOM_MR01A-01211 [mm]
  rect 0.7x1.6 smd paste+0 mask+0.05: 1(2.25,14.5) 2(1.15,14.5) 3(0.05,14.5) 4(-1.05,14.5) 5(-2.15,14.5) 6(-3.25,14.5) 7(-4.35,14.5) 8(-5.45,14.5) 9(-6.55,14.5)
  rect 1.2x1.6 smd paste+0 mask+0.05: 10(-7.75,13.9)
  rect 1.2x2.2 smd paste+0 mask+0.05: 11(-7.75,4.4) 12(7.75,4.4)
  rect 1.6x1.4 smd paste+0 mask+0.05: 13(6.85,14)
  round 0.5 hole 1 unplated paste-2539.97 mask+0.05: NPTH1(-4.95,4) NPTH2(3.05,4)
  Top Layer pour cut-out: -8.35,8.1 -8.35,12.9 -6.9,12.9 -6.9,8.1
  Top Layer pour cut-out: -6.1,10.1 2.9,10.1 2.9,8.1 -6.1,8.1
  Top Layer keep-out region: -8.35,8.1 -8.35,12.9 -6.9,12.9 -6.9,8.1
  Top Layer keep-out region: -6.1,10.1 2.9,10.1 2.9,8.1 -6.1,8.1
  silkscreen extent -7.35,-5.3 7.35,14.5, body extent -8.05,0 8.05,15, height 1.9
CON_MOLEX_53047-0210 [mm]
  oval 1x1.3 hole 0.5 mask+0.05: 1(-0.625,0) 2(0.625,0)
  silkscreen extent -2.12,-1.15 2.13,2.05, body extent -2.13,-1.15 2.13,2.05, height 4.2
CON_RJ45_YD_48F-01GYDXNL_LED-P [mm]
  rect 1.4x1.4 hole 0.9 mask+0.05: 1(-5.715,16.29)
  round 1.4 hole 0.9 mask+0.05: 2(-4.445,13.75) 3(-3.175,16.29) 4(-1.905,13.75) 5(-0.635,16.29) 6(0.635,13.75) 7(1.905,16.29) 8(3.175,13.75) 9(4.445,16.29) 10(5.715,13.75)
  round 1.5 hole 1 mask+0.05: 11(-6.63,3.34) 12(-4.09,3.34) 13(4.09,3.34) 14(6.63,3.34)
  round 2.5 hole 1.7 mask+0.05: 15(7.75,10.45) 16(-7.75,10.45)
  round 1 hole 3.2 unplated mask+0.1: 17(-5.715,7.4) 18(5.715,7.4)
  Multi-Layer keep-out circle w0.01: c5.715,7.4 r1.9
  Multi-Layer keep-out circle w0.01: c-5.715,7.4 r1.9
  silkscreen extent -11.26,-3.5 11.26,18.34, body extent -11.4,-3.5 11.39,18.34, height 17
CON_SAMTEC_FTSH-105-01-L-DV-K [mm]
  oval 0.74x2.79 smd mask+0.05: 1(-2.54,-2.035) 2(-2.54,2.035) 3(-1.27,-2.035) 4(-1.27,2.035) 5(0,-2.035) 6(0,2.035) 7(1.27,-2.035) 8(1.27,2.035) 9(2.54,-2.035) 10(2.54,2.035)
  round 0 hole 1 unplated paste-2539.97 mask+0.05: NPTH1(-1.905,0) NPTH2(1.905,0)
  silkscreen extent -3.18,-2.54 3.18,2.54, body extent -3.18,-2.92 3.18,2.92, height 6.12
CON_SAMTEC_QSH-030-01-F-D-A [mm]
  rect 0.3x2.27 smd mask+0.05: 1(7.25,2.87) 2(7.25,-2.87) 3(6.75,2.87) 4(6.75,-2.87) 5(6.25,2.87) 6(6.25,-2.87) 7(5.75,2.87) 8(5.75,-2.87) 9(5.25,2.87) 10(5.25,-2.87) 11(4.75,2.87) 12(4.75,-2.87) 13(4.25,2.87) 14(4.25,-2.87) 15(3.75,2.87) 16(3.75,-2.87) 17(3.25,2.87) 18(3.25,-2.87) 19(2.75,2.87) 20(2.75,-2.87) 21(2.25,2.87) 22(2.25,-2.87) 23(1.75,2.87) 24(1.75,-2.87) 25(1.25,2.87) 26(1.25,-2.87) 27(0.75,2.87) 28(0.75,-2.87) 29(0.25,2.87) 30(0.25,-2.87) 31(-0.25,2.87) 32(-0.25,-2.87) 33(-0.75,2.87) 34(-0.75,-2.87) 35(-1.25,2.87) 36(-1.25,-2.87) 37(-1.75,2.87) 38(-1.75,-2.87) 39(-2.25,2.87) 40(-2.25,-2.87) 41(-2.75,2.87) 42(-2.75,-2.87) 43(-3.25,2.87) 44(-3.25,-2.87) 45(-3.75,2.87) 46(-3.75,-2.87) 47(-4.25,2.87) 48(-4.25,-2.87) 49(-4.75,2.87) 50(-4.75,-2.87) 51(-5.25,2.87) 52(-5.25,-2.87) 53(-5.75,2.87) 54(-5.75,-2.87) 55(-6.25,2.87) 56(-6.25,-2.87) 57(-6.75,2.87) 58(-6.75,-2.87) 59(-7.25,2.87) 60(-7.25,-2.87)
  rect 2.54x0.43 smd mask+0.05: 61(8.063,0) 64(-8.063,0)
  rect 4.7x0.43 smd mask+0.05: 62(3.175,0) 63(-3.175,0)
  round 0.5 hole 1.05 unplated mask+0.1: 65(-10.065,-2.67) 66(10.065,-2.67)
  Multi-Layer keep-out circle w0.01: c10.065,-2.67 r0.801
  Multi-Layer keep-out circle w0.01: c-10.065,-2.67 r0.801
  silkscreen extent -10.8,-3.7 10.8,3.7, body extent -10.8,-3.75 10.8,3.75, height 3.26
CON_SAMTEC_TSW-102-07-G-S [mm]
  rect 1.85x1.85 / inner round 1.85 / far side rect 1.85x1.85 hole 1 mask+0.05: 1(-1.27,0)
  round 1.85 hole 1 mask+0.05: 2(1.27,0)
  silkscreen extent -2.58,-1.3 2.58,1.3, body extent -2.67,-1.3 2.58,1.3, height 8.38
CON_SAMTEC_TSW-103-07-F-S [mm]
  rect 1.85x1.85 / inner round 1.85 / far side rect 1.85x1.85 hole 1 mask+0.05: 1(-2.54,0)
  round 1.85 hole 1 mask+0.05: 2(0,0) 3(2.54,0)
  silkscreen extent -3.85,-1.3 3.85,1.3, body extent -3.94,-1.37 3.91,1.37, height 8.38
CON_SAMTEC_TSW-104-07-G-S [mm]
  rect 1.85x1.85 / inner round 1.85 / far side rect 1.85x1.85 hole 1 mask+0.05: 1(-3.81,0)
  round 1.85 hole 1 mask+0.05: 2(-1.27,0) 3(1.27,0) 4(3.81,0)
  silkscreen extent -5.12,-1.3 5.12,1.3, body extent -5.21,-1.37 5.18,1.37, height 8.38
CON_SAMTEC_TSW-107-07-X-D [mm] "MCD-02123"
  rect 1.85x1.85 / inner round 1.85 / far side rect 1.85x1.85 hole 1 mask+0.05: 1(-7.62,-1.27)
  round 1.85 hole 1 mask+0.05: 2(-7.62,1.27) 3(-5.08,-1.27) 4(-5.08,1.27) 5(-2.54,-1.27) 6(-2.54,1.27) 7(0,-1.27) 8(0,1.27) 9(2.54,-1.27) 10(2.54,1.27) 11(5.08,-1.27) 12(5.08,1.27) 13(7.62,-1.27) 14(7.62,1.27)
  silkscreen extent -8.89,-2.54 8.89,2.54, body extent -8.89,-2.55 8.89,2.54, height 8.38
CON_SAMTEC_TSW-120-07-G-D [mm]
  rect 1.85x1.85 / inner round 1.85 / far side rect 1.85x1.85 hole 1 mask+0.05: 1(-24.13,-1.27)
  round 1.85 hole 1 mask+0.05: 2(-24.13,1.27) 3(-21.59,-1.27) 4(-21.59,1.27) 5(-19.05,-1.27) 6(-19.05,1.27) 7(-16.51,-1.27) 8(-16.51,1.27) 9(-13.97,-1.27) 10(-13.97,1.27) 11(-11.43,-1.27) 12(-11.43,1.27) 13(-8.89,-1.27) 14(-8.89,1.27) 15(-6.35,-1.27) 16(-6.35,1.27) 17(-3.81,-1.27) 18(-3.81,1.27) 19(-1.27,-1.27) 20(-1.27,1.27) 21(1.27,-1.27) 22(1.27,1.27) 23(3.81,-1.27) 24(3.81,1.27) 25(6.35,-1.27) 26(6.35,1.27) 27(8.89,-1.27) 28(8.89,1.27) 29(11.43,-1.27) 30(11.43,1.27) 31(13.97,-1.27) 32(13.97,1.27) 33(16.51,-1.27) 34(16.51,1.27) 35(19.05,-1.27) 36(19.05,1.27) 37(21.59,-1.27) 38(21.59,1.27) 39(24.13,-1.27) 40(24.13,1.27)
  silkscreen extent -25.4,-2.54 25.4,2.54, body extent -25.4,-2.55 25.4,2.54, height 8.38
CON_TE-CONNECTIVITY_2-1734592-2_INV [mm] "MCD-03600"
  rect 0.3x1.1 smd mask+0.05: 1(5.25,1.7) 2(4.75,1.7) 3(4.25,1.7) 4(3.75,1.7) 5(3.25,1.7) 6(2.75,1.7) 7(2.25,1.7) 8(1.75,1.7) 9(1.25,1.7) 10(0.75,1.7) 11(0.25,1.7) 12(-0.25,1.7) 13(-0.75,1.7) 14(-1.25,1.7) 15(-1.75,1.7) 16(-2.25,1.7) 17(-2.75,1.7) 18(-3.25,1.7) 19(-3.75,1.7) 20(-4.25,1.7) 21(-4.75,1.7) 22(-5.25,1.7)
  rect 2.3x3.1 smd mask+0.05: S1(6.92,0) S2(-6.92,0)
  silkscreen extent -8.22,-3.06 8.21,1.35, body extent -8.22,-3.06 8.21,2.05, height 2.05
CON_TE-CONNECTIVITY_2041119-1_HALF-CARD [mm] "MCD-02227"
  rect 0.6x2 smd mask+0.05: 1(0.7,-4.1) 2(1.1,4.1) 3(1.5,-4.1) 4(1.9,4.1) 5(2.3,-4.1) 6(2.7,4.1) 7(3.1,-4.1) 8(3.5,4.1) 9(3.9,-4.1) 10(4.3,4.1) 11(4.7,-4.1) 12(5.1,4.1) 13(5.5,-4.1) 14(5.9,4.1) 15(6.3,-4.1) 16(6.7,4.1) 17(10.3,-4.1) 18(10.7,4.1) 19(11.1,-4.1) 20(11.5,4.1) 21(11.9,-4.1) 22(12.3,4.1) 23(12.7,-4.1) 24(13.1,4.1) 25(13.5,-4.1) 26(13.9,4.1) 27(14.3,-4.1) 28(14.7,4.1) 29(15.1,-4.1) 30(15.5,4.1) 31(15.9,-4.1) 32(16.3,4.1) 33(16.7,-4.1) 34(17.1,4.1) 35(17.5,-4.1) 36(17.9,4.1) 37(18.3,-4.1) 38(18.7,4.1) 39(19.1,-4.1) 40(19.5,4.1) 41(19.9,-4.1) 42(20.3,4.1) 43(20.7,-4.1) 44(21.1,4.1) 45(21.5,-4.1) 46(21.9,4.1) 47(22.3,-4.1) 48(22.7,4.1) 49(23.1,-4.1) 50(23.5,4.1) 51(23.9,-4.1) 52(24.3,4.1)
  rect 2.3x3.2 smd mask+0.05: 53(-2.15,-3.5) 54(27.15,-3.5)
  rect 5.8x5.8 hole 3.4: 55(0.4,23.9) 56(24.6,23.9)
  round 0 hole 1.6 unplated: 57(0,0)
  round 0 hole 1.1 unplated: 58(25,0)
  Top Layer keep-out region: 27.5,21 27.5,26.8 21.7,26.8 21.7,21
  Top Layer keep-out region: -2.5,21 3.3,21 3.3,26.8 -2.5,26.8
  silkscreen extent -2.45,-3.65 27.45,4.55, body extent -2.45,-4.58 27.45,4.55, height 4
CON_USB-TYPEC_AMPHENOL_12401826E412A [mm] "MCD-03232"
  round 0 hole 0.65 unplated mask+0.05: 0(-3.6,0)
  round 0 hole 0.65 slot 0.95 at 0 deg unplated mask+0.05: 0(3.6,0)
  rect 0.3x0.7 smd mask+0.05: A1(-2.75,0.66) A2(-2.25,0.66) A3(-1.75,0.66) A4(-1.25,0.66) A5(-0.75,0.66) A6(-0.25,0.66) A7(0.25,0.66) A8(0.75,0.66) A9(1.25,0.66) A10(1.75,0.66) A11(2.25,0.66) A12(2.75,0.66) B1(2.5,-1.04) B2(2,-1.04) B3(1.5,-1.04) B4(1,-1.04) B5(0.5,-1.04) B6(0,-1.04) B7(-0.5,-1.04) B8(-1,-1.04) B9(-1.5,-1.04) B10(-2,-1.04) B11(-2.5,-1.04) B12(-3,-1.04)
  oval 0.8x1.4 hole 0.5 slot 1.1 at 90 deg mask+0.05: SH1(-4.13,-1.25) SH2(4.13,-1.25) SH3(-4.49,-4.7) SH4(4.49,-4.7)
  Top Layer keep-out region: -3.75,-7.24 3.75,-7.24 3.75,-1.95 -3.75,-1.95
  silkscreen extent -4.7,-9.59 4.7,0.91, body extent -4.6,-9.59 4.6,0.91, height 3.25
CPOL_TCJ-B_1210_H210 [mm] "MCD-01791"
  rect 1.35x2.8 smd mask+0.05: 1(-1.375,0) 2(1.375,0)
  silkscreen extent -2.33,-1.68 1.85,1.68, body extent -1.85,-1.5 1.85,1.5, height 2.11
CPOL_WURTH_WCAP-ASLL_8X10P5 [mm] "MCD-01683"
  rect 4.2x1.9 smd mask+0.05: 1(3.5,0) 2(-3.5,0)
  silkscreen extent -4.15,-4.15 4.22,4.15, body extent -4.5,-4.15 4.5,4.15, height 10.5
CRY_NX2012SA_2P [mm]
  rect 1x1.25 smd mask+0.05: 1(-0.75,0) 2(0.75,0)
  silkscreen extent -1.05,-0.75 1.05,0.75, body extent -1.05,-0.63 1.05,0.63, height 0.6
CRY_NX2016SA_4P [mm]
  rect 0.85x0.75 smd mask+0.05: 1(-0.675,-0.525) 2(0.675,-0.525) 3(0.675,0.525) 4(-0.675,0.525)
  silkscreen extent -1.22,-1.02 1.05,0.85, body extent -1.05,-0.85 1.05,0.85, height 0.7
CRY_NX3225HA_4P [mm]
  rect 1.4x1.2 smd mask+0.05: 1(-1.1,-0.8) 2(1.1,-0.8) 3(1.1,0.8) 4(-1.1,0.8)
  silkscreen extent -1.9,-1.5 1.65,1.3, body extent -1.66,-1.31 1.66,1.31, height 0.91
CRY_NZ1612SH_4P [mm] "MCD-02343"
  rect 0.6x0.5 smd mask+0.05: 1(-0.55,-0.4) 2(0.55,-0.4) 3(0.55,0.4) 4(-0.55,0.4)
  silkscreen extent -0.97,-0.77 0.85,0.65, body extent -0.85,-0.65 0.85,0.65, height 0.71
DIO_SOD323 [mm]
  rect 1.06x0.54 smd mask+0.05: 1(-1.07,0) 2(1.07,0)
  silkscreen extent -0.9,-0.72 0.9,0.72, body extent -1.3,-0.78 1.3,0.78, height 1.17
DIO_SOD323_1A_2K [mm]
  rect 1.06x0.54 smd mask+0.05: 1(-1.07,0) 2(1.07,0)
  silkscreen extent -0.9,-0.72 0.9,0.72, body extent -1.3,-0.78 1.3,0.78, height 1.17
DIO_SOT23 [mm]
  rect 1x1.4 smd mask+0.05: 1(-0.95,-1.1) 2(0.95,-1.1) 3(0,1.1)
  silkscreen extent -1.63,-0.82 1.63,0.82, body extent -1.56,-1.25 1.56,1.25, height 1.1
ESD_QFN1610_2N_1K_2A [mm] "DFN, 2-Leads, Body 1.60x1.00mm"
  rect 0.55x0.9 smd mask+0.05: 1(-0.625,0) 2(0.625,0)
  silkscreen extent -1.02,-0.58 0.85,0.58, body extent -0.85,-0.55 0.85,0.55, height 0.6
ESD_QFN-6L_1P7X1P5_P050 [mm]
  rect 0.25x0.6 smd mask+0.05: 1(-0.5,-0.65) 2(0,-0.65) 3(0.5,-0.65) 4(0.5,0.65) 5(0,0.65) 6(-0.5,0.65)
  silkscreen extent -0.9,-0.8 0.9,0.8, body extent -0.9,-0.8 0.9,0.8, height 0.56
ESD_SOT23 [mm]
  rect 1x1.4 smd mask+0.05: 1(-0.95,-1.1) 2(0.95,-1.1) 3(0,1.1)
  silkscreen extent -1.63,-0.82 1.63,0.82, body extent -1.56,-1.5 1.56,1.5, height 1.4
ESD_ST0201 [mm]
  rect 0.425x0.33 smd mask+0.05: 1(-0.312,0) 2(0.312,0)
  silkscreen extent -0.55,-0.3 -0.5,0.3, body extent -0.34,-0.18 0.34,0.18, height 0.34
ESD_UQFN-6L_1P45X1P4_P040 [mm] "MCD-03060"
  rect 0.2x0.7 smd mask+0.05: 1(-0.4,-0.525) 2(0,-0.525) 3(0.4,-0.525) 4(0.4,0.525) 5(0,0.525) 6(-0.4,0.525)
  body extent -0.72,-0.7 0.72,0.7, height 0.51
ESD_UQFN-10L_2P5X1_P050 [mm]
  rect 0.2x0.58 smd mask+0.05: 1(-1,-0.41) 2(-0.5,-0.41) 4(0.5,-0.41) 5(1,-0.41) 6(1,0.41) 7(0.5,0.41) 9(-0.5,0.41) 10(-1,0.41)
  rect 0.4x0.58 smd mask+0.05: 3(0,-0.41) 8(0,0.41)
  silkscreen extent -1.38,-0.63 1.38,0.63, body extent -1.3,-0.55 1.3,0.55, height 0.51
